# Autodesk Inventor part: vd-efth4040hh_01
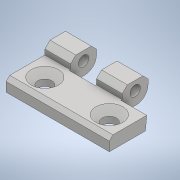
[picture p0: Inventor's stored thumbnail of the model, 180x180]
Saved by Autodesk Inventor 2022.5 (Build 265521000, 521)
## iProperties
Created: 2019-12
Part Number: vd-efth4040hh_01
Material: 一般
Document SubType Name: Modeling
Designer: ImaoCorp
Density: 1 g/cm^3
Appearance: 既定
Author: ImaoCorp
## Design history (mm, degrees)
feature "vd-efth4040hh_01"
node "ソリッド1"
